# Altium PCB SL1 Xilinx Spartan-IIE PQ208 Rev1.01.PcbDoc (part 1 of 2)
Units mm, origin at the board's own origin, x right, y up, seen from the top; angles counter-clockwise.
Board outline 180.01 x 50.51 mm, 2 copper layers (Top Layer, Bottom Layer), stack 1.646 mm thick; 115 components, 126 nets, 642 pads, 225 vias.
Unrouted connection lines stored in the file: 2.
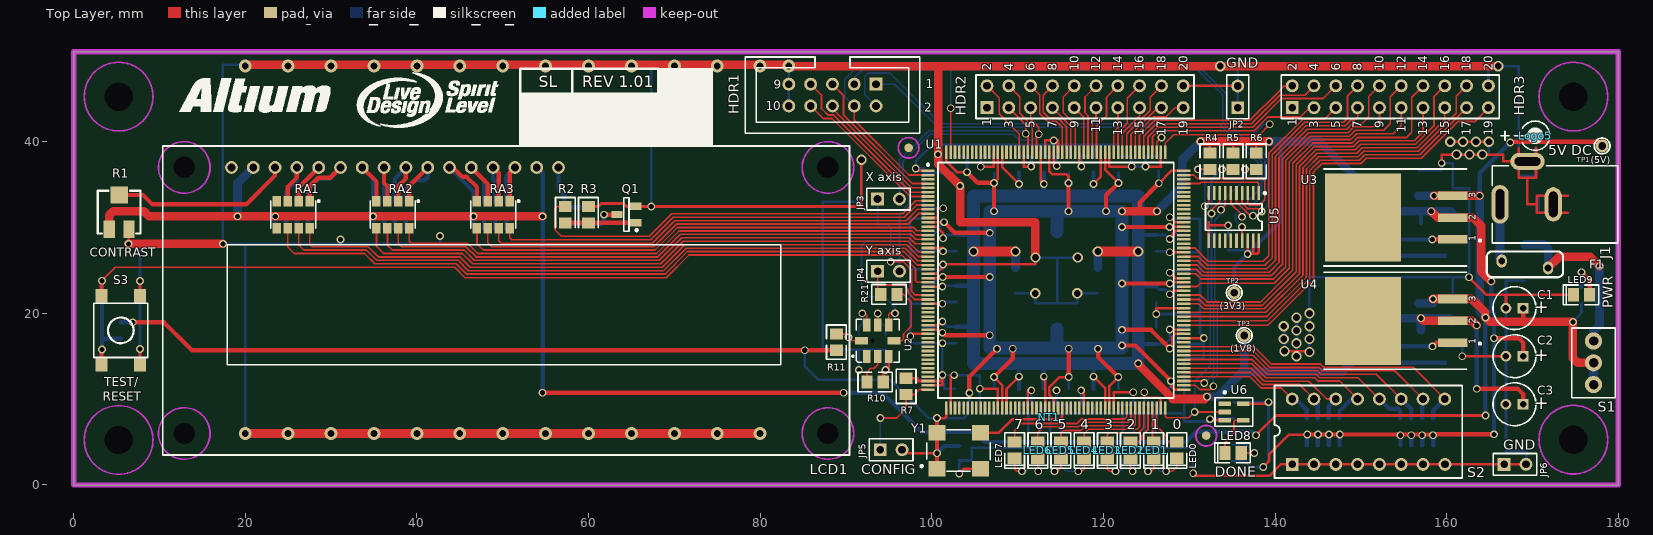
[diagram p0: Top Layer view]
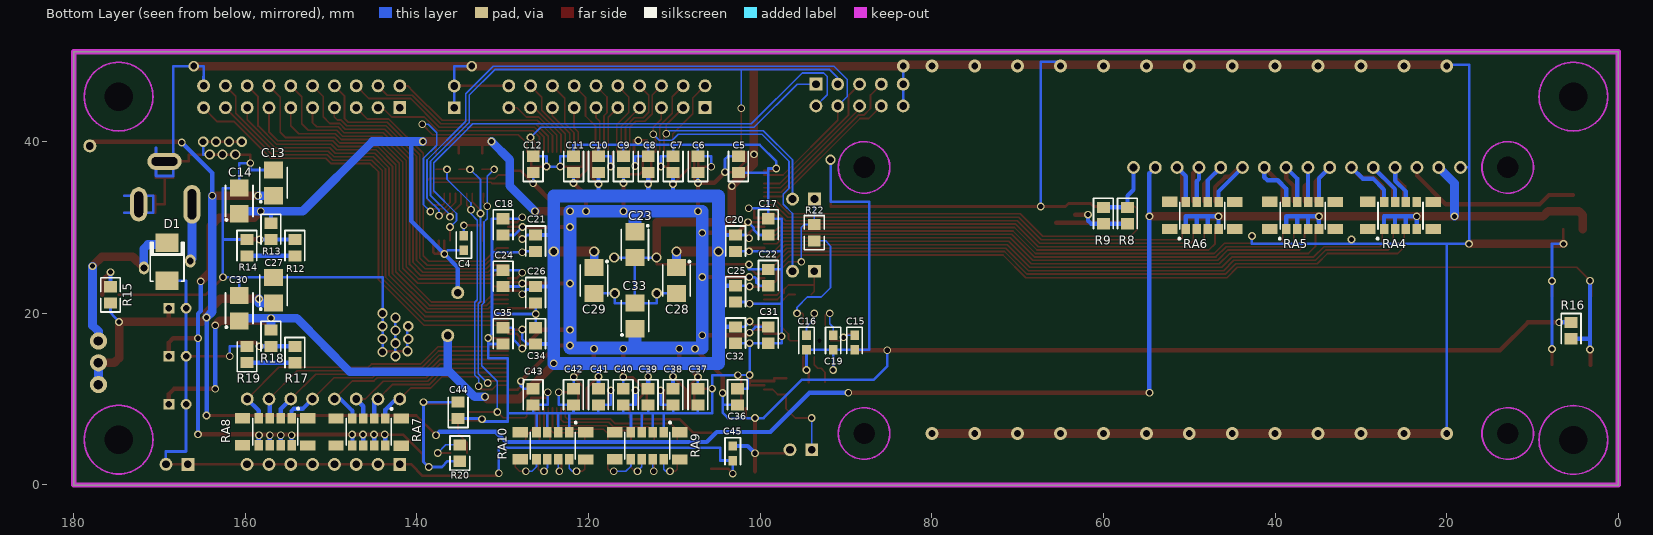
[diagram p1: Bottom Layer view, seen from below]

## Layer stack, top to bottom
Top Solder: solder mask 0.0102, Solder Resist, Dk 3.5
Top Layer: signal copper 0.0356
Dielectric1: core 1.5748, FR-4, Dk 4.8
Bottom Layer: signal copper 0.0356
Bottom Solder: solder mask 0.0102, Solder Resist, Dk 3.5

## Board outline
0,-0.005 cw(c0,0) -0.005,0 -0.005,50.5 cw(c0,50.5) 0,50.505 180,50.505 cw(c180,50.5) 180.005,50.5 180.005,0 cw(c180,0) 180,-0.005

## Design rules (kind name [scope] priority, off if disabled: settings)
Clearance "Clearance_Power Polygon" [inpolygon and innetclass('Power')] p1: gap=0.3 ignorepadtopadclearanceinfootprint=FALSE except(0: Arc-Hole Track-Hole SMDPad-Hole THPad-Hole Via-Hole Fill-Hole Poly-Hole Region-Hole Text-Hole)
Clearance [All] p2: gap=0.2 ignorepadtopadclearanceinfootprint=FALSE except(0: Arc-Hole Track-Hole SMDPad-Hole THPad-Hole Via-Hole Fill-Hole Poly-Hole Region-Hole Text-Hole) // General
ComponentClearance ComponentClearance_D1_F1 [InComponent('D1') vs InComponent('F1')] p1 off: gap=0.03 collisioncheckmode=3 verticalgap=0.254 showdistances=FALSE
ComponentClearance ComponentClearance_JP4_R21 [InComponent('JP4') vs InComponent('R21')] p2 off: gap=0.07 collisioncheckmode=3 verticalgap=0.254 showdistances=FALSE
ComponentClearance ComponentClearance_LCD1_U2 [InComponent('LCD1') vs InComponent('U2')] p3 off: gap=0.09 collisioncheckmode=3 verticalgap=0.254 showdistances=FALSE
ComponentClearance ComponentClearance_U1_U6 [InComponent('U1') vs InComponent('U6')] p4 off: gap=0.1 collisioncheckmode=3 verticalgap=0.254 showdistances=FALSE
ComponentClearance ComponentClearance_S2 [InComponent('S2') vs InComponent('RA7') Or InComponent('RA8')] p5 off: gap=0.1 collisioncheckmode=3 verticalgap=0.254 showdistances=FALSE // Why is such a small clearance necessary?
ComponentClearance ComponentClearance_LCD1_R11 [InComponent('LCD1') vs InComponent('R11')] p6 off: gap=0.16 collisioncheckmode=3 verticalgap=0.254 showdistances=FALSE
ComponentClearance ComponentClearance_J1_Logo5 [InComponent('J1') vs InComponent('Logo5')] p7 off: gap=0.19 collisioncheckmode=3 verticalgap=0.254 showdistances=FALSE
ComponentClearance ComponentClearance_R2_R3 [InComponent('R2') vs InComponent('R3')] p8 off: gap=0.19 collisioncheckmode=3 verticalgap=0.254 showdistances=FALSE
ComponentClearance ComponentClearance_R5 [InComponent('R5') vs InComponent('R4') Or InComponent('R6')] p9 off: gap=0.19 collisioncheckmode=3 verticalgap=0.254 showdistances=FALSE
ComponentClearance ComponentClearance_LEDs [HasFootprint('SMD _LED') vs HasFootprint('SMD _LED')] p10 off: gap=0.19 collisioncheckmode=3 verticalgap=0.254 showdistances=FALSE
ComponentClearance ComponentClearance_R7_R10 [InComponent('R7') vs InComponent('R10')] p11 off: gap=0.24 collisioncheckmode=3 verticalgap=0.254 showdistances=FALSE
ComponentClearance ComponentClearance_U1 [InComponent('U1') vs Not InComponent('NT1') && Not InComponent('LED8')] p12 off: gap=0.254 collisioncheckmode=3 verticalgap=0.254 showdistances=FALSE
ComponentClearance ComponentClearance_General [Not InComponent('U1') vs Not InComponent('U1')] p13 off: gap=0.254 collisioncheckmode=3 verticalgap=0.254 showdistances=FALSE
ComponentClearance ComponentClearance_Default [All] p14: gap=0.127 collisioncheckmode=3 verticalgap=0.254 showdistances=FALSE
FabricationTestPointUsage TestPointUsage [All] p1 off: valid=0 allowmultiple=FALSE
FabricationTestpoint Testpoint [All] p1 off: side=3 testpointundercomponent=TRUE minsize=1.016 maxsize=2.54 preferedsize=1.524 minholesize=0 maxholesize=1.016 preferedholesize=0.813 testpointgrid=0.025 allowsidetop=TRUE allowsidebottom=TRUE usegrid=TRUE gridtolerance=0
HoleSize [All] p1: absolutevalues=TRUE maxlimit=3.302 minlimit=0 maxpercent=80.000 minpercent=20.000
PlaneConnect [All] p1: planeconnectstyle=Relief reliefexpansion=0.3 reliefentries=4 reliefconductorwidth=0.2 reliefairgap=0.2
PolygonConnect PolygonConnect_Power [innetclass('Power')] p1: connectstyle=Relief reliefconductorwidth=0.3 reliefentries=4 polygonreliefangle="90 Angle" airgapwidth=0.254
PolygonConnect [All] p2: connectstyle=Relief reliefconductorwidth=0.2 reliefentries=4 polygonreliefangle="90 Angle" airgapwidth=0.254
RoutingVias RoutingVias_Power [innetclass('Power')] p1: holewidth=0.6 width=0.9 viastyle="Through Hole" minholewidth=0.6 minwidth=0.9 maxholewidth=0.8 maxwidth=1.5
RoutingVias [All] p2: holewidth=0.6 width=0.9 viastyle="Through Hole" minholewidth=0.6 minwidth=0.9 maxholewidth=0.6 maxwidth=0.9
SilkToSolderMaskClearance SilkscreenOverComponentPads [IsPad] p1: minsilkscreentomaskgap=0.254 clearancetoexposedcopper=TRUE
SolderMaskExpansion SolderMaskExpansion_Power_Vias [isvia] p1: expansion=0 istentingtop=FALSE
SolderMaskExpansion [All] p2: expansion=0.1 istentingtop=FALSE
Width Width_Power [innetclass('Power') and not inpolygon] p1: maxlimit=2 minlimit=0.3 preferedwidth=0.3
Width [All] p2: maxlimit=2 minlimit=0.2 preferedwidth=0.2
24 further rules are at their usual default settings.

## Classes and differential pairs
component class U_SL_LCD_SW_LED: LCD1 LED0 LED1 LED2 LED3 LED4 LED5 LED6 LED7 Q1 R1 R2 R3 R8 R9 R16 RA1 RA2 RA3 RA4 RA5 RA6 RA7 RA8 RA9 RA10 S2 S3
component class U_SL_FPGA_Auto_2E: U1
component class U_SL_Config: C4 C44 LED8 R4 R5 R6 R20 U5 U6
component class SL_FPGA_Manual_2E: C1 C2 C3 C5 C6 C7 C8 C9 C10 C11 C12 C13 C14 C17 C18 C20 C21 C22 C23 C24 C25 C26 C27 C28 C29 C30 C31 C32 C33 C34 C35 C36 C37 C38 C39 C40 C41 C42 C43 D1 F1 J1 JP2 JP6 LED9 R12 R13 R14 R15 R17 R18 R19 S1 TP1 TP2 TP3 U3 U4
net class SW[7..0]: SW0 SW1 SW2 SW3 SW4 SW5 SW6 SW7
net class LEDS[7..0]: LEDS0 LEDS1 LEDS2 LEDS3 LEDS4 LEDS5 LEDS6 LEDS7
net class LCD_DB[7..0]: LCD_DB0 LCD_DB1 LCD_DB2 LCD_DB3 LCD_DB4 LCD_DB5 LCD_DB6 LCD_DB7
net class Power: 5V GND VCCINT VCCO

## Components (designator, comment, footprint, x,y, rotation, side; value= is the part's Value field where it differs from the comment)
C1 "100uF 16V" CAPPR2-5X6.8 167.9,20.6 r180 top
C2 "100uF 16V" CAPPR2-5X6.8 167.9,15 r180 top
C3 "100uF 16V" CAPPR2-5X6.8 167.9,9.4 r180 top
C4 "10nF" CC1608-0603 134.525,28.2 r90 bottom
C5 "0.1uF" CC2012-0805 102.55,37.35 r90 bottom
C6 "0.1uF" CC2012-0805 107.25,37.35 r90 bottom
C7 "0.1uF" CC2012-0805 110.15,37.35 r90 bottom
C8 "0.1uF" CC2012-0805 113.05,37.35 r90 bottom
C9 "0.1uF" CC2012-0805 115.95,37.35 r90 bottom
C10 "0.1uF" CC2012-0805 118.85,37.35 r90 bottom
C11 "0.1uF" CC2012-0805 121.75,37.35 r90 bottom
C12 "0.1uF" CC2012-0805 126.45,37.35 r90 bottom
C13 "10uF" MCCT-B 156.7,35.2 r90 bottom
C14 "10uF" MCCT-B 160.7,33.1 r90 bottom
C15 "100nF" CC1608-0603 89,16.6 r270 bottom
C16 "100nF" CC1608-0603 94.6,16.6 r270 bottom
C17 "0.1uF" CC2012-0805 99.05,30.075 r270 bottom
C18 "0.1uF" CC2012-0805 129.95,30.075 r270 bottom
C19 "100nF" CC1608-0603 91.5,16.6 r270 bottom
C20 "0.1uF" CC2012-0805 102.85,28.175 r270 bottom
C21 "0.1uF" CC2012-0805 126.15,28.175 r270 bottom
C22 "0.1uF" CC2012-0805 99.05,24.175 r270 bottom
C23 "10uF" MCCT-B 114.6,28 r270 bottom
C24 "0.1uF" CC2012-0805 129.95,24.075 r270 bottom
C25 "0.1uF" CC2012-0805 102.85,22.275 r270 bottom
C26 "0.1uF" CC2012-0805 126.15,22.175 r270 bottom
C27 "10uF" MCCT-B 156.7,22.7 r90 bottom
C28 "10uF" MCCT-B 109.75,23.825 r270 bottom
C29 "10uF" MCCT-B 119.35,23.825 r270 bottom
C30 "10uF" MCCT-B 160.7,20.6 r90 bottom
C31 "0.1uF" CC2012-0805 99.05,17.475 r270 bottom
C32 "0.1uF" CC2012-0805 102.85,17.475 r270 bottom
C33 "10uF" MCCT-B 114.6,19.7 r90 bottom
C34 "0.1uF" CC2012-0805 126.15,17.375 r270 bottom
C35 "0.1uF" CC2012-0805 129.95,17.375 r270 bottom
C36 "0.1uF" CC2012-0805 102.65,10.275 r270 bottom
C37 "0.1uF" CC2012-0805 107.25,10.275 r270 bottom
C38 "0.1uF" CC2012-0805 110.15,10.275 r270 bottom
C39 "0.1uF" CC2012-0805 113.05,10.275 r270 bottom
C40 "0.1uF" CC2012-0805 115.95,10.275 r270 bottom
C41 "0.1uF" CC2012-0805 118.85,10.275 r270 bottom
C42 "0.1uF" CC2012-0805 121.75,10.275 r270 bottom
C43 "0.1uF" CC2012-0805 126.45,10.275 r270 bottom
C44 "0.1uF" CC2012-0805 135.2,8.7 r90 bottom
C45 "10nF" CC1608-0603 103.2,3.7 r270 bottom
D1 "SM6T6V8A" DO214 169.1,25.999 r90 bottom
F1 "Polyswitch, 1.1A" RUE160_0.2 169.1,25.7 r0 top
HDR1 "Header 5X2" HDR2X5_LP 93.5,46.7 r0 top
HDR2 "Header 10X2" HDR2X10 106.44,43.96 r0 top locked
HDR3 "Header 10X2" HDR2X10 142,43.96 r0 top locked
J1 "KLD-0202-B" KLD-0202 179.9,32.7 r180 top
JP2 "GND" HDR1X2 135.65,43.96 r90 top locked
JP3 "X axis" HDR1X2 93.693,33.31 r0 top
JP4 "Y axis" HDR1X2 93.7,24.9 r0 top
JP5 "CONFIG" HDR1X2 94,4.1 r0 top
JP6 "GND" HDR1X2 166.7,2.4 r0 top
LCD1 "162A" 162A 18.4,37 r0 top locked
LED0 "HSMH-C170" "SMD _LED" 128.55,4.075 r90 top
LED1 "HSMH-C170" "SMD _LED" 125.85,4.075 r90 top
LED2 "HSMH-C170" "SMD _LED" 123.15,4.075 r90 top
LED3 "HSMH-C170" "SMD _LED" 120.45,4.075 r90 top
LED4 "HSMH-C170" "SMD _LED" 117.75,4.075 r90 top
LED5 "HSMH-C170" "SMD _LED" 115.05,4.075 r90 top
LED6 "HSMH-C170" "SMD _LED" 112.35,4.075 r90 top
LED7 "HSMH-C170" "SMD _LED" 109.65,4.075 r90 top
LED8 "HSMH-C170" "SMD _LED" 135.1,3.725 r0 top
LED9 "HSMH-C170" "SMD _LED" 175.7,22.15 r0 top
Logo5 "5V" "5V SYMBOL" 170.3,40.7 r0 top
NT1 "GND" NT 113.686,8.174 r270 top net-tie
Q1 "2N7002" SO-G3 64.4,31.5 r90 top
R1 "20K" POT4MM-2 5.3,31.8 r90 top
R2 "560R" CC2012-0805 57.3,31.5 r270 top
R3 "10K" CC2012-0805 60,31.5 r270 top
R4 "4K7" CR2012-0805 132.4,37.725 r270 top
R5 "4K7" CR2012-0805 135.1,37.725 r270 top
R6 "4K7" CR2012-0805 137.8,37.725 r270 top
R7 "1K" CR2012-0805 97,11.5 r270 top
R8 "68R" CC2012-0805 57.2,31.4 r270 bottom
R9 "68R" CC2012-0805 60,31.4 r270 bottom
R10 "680R" CR2012-0805 93.4,12 r180 top
R11 "0R" CR2012-0805 88.88,16.65 r90 top
R12 "100R" CC2012-0805 154.2,27.65 r270 bottom
R13 "120R" CC2012-0805 157,29.55 r270 bottom
R14 "100R" CC2012-0805 159.8,27.65 r270 bottom
R15 "270R" CR2012-0805 175.7,22.15 r270 bottom
R16 "4K7" CC2012-0805 5.5,18 r270 bottom
R17 "47R" CC2012-0805 154.2,15.2 r270 bottom
R18 "120R" CC2012-0805 157,17.1 r270 bottom
R19 "5R6" CC2012-0805 159.8,15.2 r90 bottom
R20 "270R" CR2012-0805 135,3.725 r270 bottom
R21 "100R" CR2012-0805 95,22.2 r0 top
R22 "100R" CR2012-0805 93.7,29.4 r270 bottom
RA1 "270R" MNR34 25.6,31.5 r270 top
RA2 "270R" MNR34 37.2,31.5 r270 top
RA3 "270R" MNR34 48.9,31.5 r270 top
RA4 "4K7" MNR34T 25.4,31.4 r270 bottom
RA5 "4K7" MNR34T 36.8,31.4 r270 bottom
RA6 "4K7" MNR34T 48.5,31.4 r270 bottom
RA7 "4K7" MNR34T 145.605,6.174 r90 bottom
RA8 "4K7" MNR34T 156.5,6.2 r90 bottom
RA9 "270R" MNR34T 113.15,4.575 r90 bottom
RA10 "270R" MNR34T 124.15,4.575 r90 bottom
S1 "TL36WW050" PCB_SWITCH 177.105,11.689 r90 top
S2 "A6ER-8104" DIP-16-KEY 142,2.4 r0 top
S3 "DTSM-61-NR" B3FS_SWITCH 5.5,18 r270 top
TP1 "(5V)" TP 178.1,39.5 r0 top
TP2 "(3V3)" TP 135.233,22.4 r0 top
TP3 "(1V8)" TP 136.4,17.4 r0 top
U1 "XC2S300E-6PQ208C" PQ208 114.45,23.875 r0 top locked
U2 "ADXL202E" E-8 93.7,16.8 r90 top
U3 "LM1084IS-ADJ" TO-263 160.7,28.62 r90 top
U4 "LM1084IS-ADJ" TO-263 160.7,16.6 r90 top
U5 "XCF02SVO20C" VO20 135.175,31.225 r180 top
U6 "SN74LVC1G04DBV" SO-G5/P.95 135.2,8.5 r270 top
Y1 "25MHz" QSMO_4200 100.6,1.5 r0 top

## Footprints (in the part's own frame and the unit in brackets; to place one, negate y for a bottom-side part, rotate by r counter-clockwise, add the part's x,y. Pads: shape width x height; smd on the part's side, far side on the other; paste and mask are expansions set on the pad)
"5V SYMBOL" [mm]
  silkscreen extent -4.01,-1.71 1.7,1.71
162A [mm]
  round 1.5 hole 0.9: 1(0,0) 2(2.54,0) 3(5.08,0) 4(7.62,0) 5(10.16,0) 6(12.7,0) 7(15.24,0) 8(17.78,0) 9(20.32,0) 10(22.86,0) 11(25.4,0) 12(27.94,0) 13(30.48,0) 14(33.02,0) 15(35.56,0) 16(38.1,0)
  round 2.3 hole 2.5 unplated: M1(-5.5,0) M2(69.5,0) M3(-5.5,-31) M4(69.5,-31)
  Keep-Out Layer circle w0.2: c69.5,0 r3
  Keep-Out Layer circle w0.2: c69.5,-31 r3
  Keep-Out Layer circle w0.2: c-5.5,-31 r3
  Keep-Out Layer circle w0.2: c-5.5,0 r3
  silkscreen extent -8,-33.5 72,2.5, body extent -8.01,-33.5 72,2.5, height 10.16
B3FS_SWITCH [mm]
  rect 1.6x1.4 smd: 1(3.998,-2.244) 2(-4.012,-2.244) 3(3.998,2.246) 4(-4.012,2.246)
  silkscreen extent -3.17,-3.15 3.14,3.16, body extent -4.57,-3.15 4.57,3.16, height 4.57
CAPPR2-5X6.8 [mm]
  rect 1.25x1.25 hole 0.75: 1(-0.994,-0.009)
  round 1.25 hole 0.75: 2(1.006,-0.009)
  silkscreen extent -2.49,-2.51 2.5,2.49, body extent -2.49,-2.51 2.51,2.49, height 10.16
CC1608-0603 [mm]
  rect 1.1x1 smd: 1(-0.843,0.001) 2(0.857,0.001)
  silkscreen extent -1.79,-0.9 1.31,0.9, body extent -1.46,-0.57 1.46,0.57, height 0.76
CC2012-0805 [mm]
  rect 1.3x1.5 smd: 1(-0.945,-0.007) 2(0.955,-0.007)
  silkscreen extent -1.99,-1.16 1.51,1.14, body extent -1.52,-0.7 1.52,0.7, height 0.76
CR2012-0805 [mm]
  rect 1.3x1.5 smd: 1(-0.946,0) 2(0.954,0)
  silkscreen extent -2,-1.15 2,1.15, body extent -1.52,-0.7 1.52,0.7, height 0.76
DIP-16-KEY [mm]
  rect 1.5x1.5 hole 0.9: 1(-0.011,0.001)
  round 1.5 hole 0.9: 2(2.529,0.001) 3(5.069,0.001) 4(7.609,0.001) 5(10.149,0.001) 6(12.689,0.001) 7(15.229,0.001) 8(17.789,0.001) 9(17.769,7.621) 10(15.229,7.621) 11(12.689,7.621) 12(10.149,7.621) 13(7.609,7.621) 14(5.069,7.621) 15(2.529,7.621) 16(-0.011,7.621)
  silkscreen extent -2.06,-1.59 19.82,9.2, body extent -2.03,-1.52 19.81,9.14, height 7.11
DO214 [mm]
  rect 2.159x2.7 smd: 1(-2.21,0.005) 2(2.235,0.005)
  silkscreen extent -2.27,-1.96 2.3,1.97, body extent -3.17,-1.27 3.17,1.27, height 1.27
E-8 [mil]
  round 15 hole 20 unplated: 0(-0.02,23.98)
  rect 60x35 smd: 1(-72.85,49.98) 2(-72.85,-0.02) 3(-72.85,-50.02) 5(72.82,-50.02) 6(72.82,-0.02) 7(72.82,49.98)
  rect 35x60 smd: 4(-0.02,-74.82) 8(-0.02,74.79)
  silkscreen extent -98,-98 99,118, body extent -95,-95 95,95, height 80
HDR1X2 [mm]
  rect 1.5x1.5 hole 0.9: 1(-0.011,0.007)
  round 1.5 hole 0.9: 2(2.529,0.007)
  silkscreen extent -1.28,-1.26 3.8,1.28, body extent -1.27,-1.27 3.81,1.27, height 10
HDR2X5_LP [mm]
  rect 1.5x1.5 hole 0.9: 1(0.003,0.004)
  round 1.5 hole 0.9: 2(0.003,-2.536) 3(-2.537,0.004) 4(-2.537,-2.536) 5(-5.077,0.004) 6(-5.077,-2.536) 7(-7.617,0.004) 8(-7.617,-2.536) 9(-10.157,0.004) 10(-10.157,-2.536)
  silkscreen extent -15.24,-5.71 5.08,3.18, body extent -15.24,-5.71 5.08,3.18, height 10
HDR2X10 [mm]
  rect 1.5x1.5 hole 0.9: 1(-0.011,0.007)
  round 1.5 hole 0.9: 2(-0.011,2.547) 3(2.529,0.007) 4(2.529,2.547) 5(5.069,0.007) 6(5.069,2.547) 7(7.609,0.007) 8(7.609,2.547) 9(10.149,0.007) 10(10.149,2.547) 11(12.689,0.007) 12(12.689,2.547) 13(15.229,0.007) 14(15.229,2.547) 15(17.769,0.007) 16(17.769,2.547) 17(20.309,0.007) 18(20.309,2.547) 19(22.849,0.007) 20(22.849,2.547)
  silkscreen extent -1.28,-1.26 24.12,3.82, body extent -1.27,-1.27 24.13,3.81, height 10
KLD-0202 [mm]
  oval 2x4.5 hole 1 slot 3.5 at 90 deg: 1(13.692,-0.001)
  oval 2x4 hole 1 slot 3 at 90 deg: 2(7.492,-0.001)
  oval 4x2 hole 1 slot 3 at 0 deg: 3(10.492,-5.001)
  silkscreen extent -0.01,-4.5 14.59,4.5, body extent 0,-4.44 14.6,4.45, height 7.62
MCCT-B [mm]
  rect 2x2.2 smd: 1(-1.505,-0.002) 2(1.495,-0.002)
  silkscreen extent -2.3,-1.6 1.8,1.6, body extent -2.29,-0.89 2.29,0.89, height 1.27
MNR34 [mm]
  rect 1.2x1 smd: 1(-1.578,1.898) 2(-1.578,0.628) 3(-1.578,-0.642) 4(-1.578,-1.912) 5(1.572,-1.912) 6(1.572,-0.642) 7(1.572,0.628) 8(1.572,1.898)
  silkscreen extent -1.68,-2.62 1.55,3.06, body extent -2.03,-2.29 2.03,2.29, height 1.27
MNR34T [mm]
  rect 1.2x1 smd: 1(1.575,-1.896) 2(1.575,-0.626) 3(1.575,0.644) 4(1.575,1.914) 5(-1.575,1.914) 6(-1.575,0.644) 7(-1.575,-0.626) 8(-1.575,-1.896)
  rect 1.2x1.8 smd: STP(-1.6,-3.801) STP(-1.575,3.819) STP(1.575,-3.801) STP(1.575,3.819)
  silkscreen extent -1.55,-2.76 2.79,2.62, body extent -1.65,-2.71 1.68,2.72, height 2
NT [mm]
  rect 0.2x0.2 smd: 1(0.01,0.011) 2(0.51,0.011)
  Top Layer lines w0.3: 0.51,0.011 0.01,0.011
PCB_SWITCH [mm]
  round 2 hole 1.1: 1(0.011,0.005) 2(2.551,0.005) 3(5.091,0.005)
  silkscreen extent -1.54,-2.53 6.59,2.55, body extent -1.52,-2.54 6.6,2.54, height 15
POT4MM-2 [mm]
  rect 2x1.3 smd: CCW(-2.008,-1.162) CW(-2.008,1.138)
  rect 2x2 smd: W(1.992,-0.012)
  silkscreen extent -2.51,-2.51 2.49,2.49, body extent -2.92,-2.41 2.92,2.41, height 3.05
PQ208 [mm]
  rect 1.55x0.3 smd: 1(-14.902,12.738) 2(-14.902,12.238) 3(-14.902,11.738) 4(-14.902,11.238) 5(-14.902,10.738) 6(-14.902,10.238) 7(-14.902,9.738) 8(-14.902,9.238) 9(-14.902,8.738) 10(-14.902,8.238) 11(-14.902,7.738) 12(-14.902,7.238) 13(-14.902,6.738) 14(-14.902,6.238) 15(-14.902,5.738) 16(-14.902,5.238) 17(-14.902,4.738) 18(-14.902,4.238) 19(-14.902,3.738) 20(-14.902,3.238) 21(-14.902,2.738) 22(-14.902,2.238) 23(-14.902,1.738) 24(-14.902,1.238) 25(-14.902,0.738) 26(-14.902,0.238) 27(-14.902,-0.262) 28(-14.902,-0.762) 29(-14.902,-1.262) 30(-14.902,-1.762) 31(-14.902,-2.262) 32(-14.902,-2.762) 33(-14.902,-3.262) 34(-14.902,-3.762) 35(-14.902,-4.262) 36(-14.902,-4.762) 37(-14.902,-5.262) 38(-14.902,-5.762) 39(-14.902,-6.262) 40(-14.902,-6.762) 41(-14.902,-7.262) 42(-14.902,-7.762) 43(-14.902,-8.262) 44(-14.902,-8.762) 45(-14.902,-9.262) 46(-14.902,-9.762) 47(-14.902,-10.262) 48(-14.902,-10.762) 49(-14.902,-11.262) 50(-14.902,-11.762) 51(-14.902,-12.262) 52(-14.902,-12.762) 105(14.898,-12.762) 106(14.898,-12.262) 107(14.898,-11.762) 108(14.898,-11.262) 109(14.898,-10.762) 110(14.898,-10.262) 111(14.898,-9.762) 112(14.898,-9.262) 113(14.898,-8.762) 114(14.898,-8.262) 115(14.898,-7.762) 116(14.898,-7.262) 117(14.898,-6.762) 118(14.898,-6.262) 119(14.898,-5.762) 120(14.898,-5.262) 121(14.898,-4.762) 122(14.898,-4.262) 123(14.898,-3.762) 124(14.898,-3.262) 125(14.898,-2.762) 126(14.898,-2.262) 127(14.898,-1.762) 128(14.898,-1.262) 129(14.898,-0.762) 130(14.898,-0.262) 131(14.898,0.238) 132(14.898,0.738) 133(14.898,1.238) 134(14.898,1.738) 135(14.898,2.238) 136(14.898,2.738) 137(14.898,3.238) 138(14.898,3.738) 139(14.898,4.238) 140(14.898,4.738) 141(14.898,5.238) 142(14.898,5.738) 143(14.898,6.238) 144(14.898,6.738) 145(14.898,7.238) 146(14.898,7.738) 147(14.898,8.238) 148(14.898,8.738) 149(14.898,9.238) 150(14.898,9.738) 151(14.898,10.238) 152(14.898,10.738) 153(14.898,11.238) 154(14.898,11.738) 155(14.898,12.238) 156(14.898,12.738)
  rect 0.3x1.55 smd: 53(-12.752,-14.912) 54(-12.252,-14.912) 55(-11.752,-14.912) 56(-11.252,-14.912) 57(-10.752,-14.912) 58(-10.252,-14.912) 59(-9.752,-14.912) 60(-9.252,-14.912) 61(-8.752,-14.912) 62(-8.252,-14.912) 63(-7.752,-14.912) 64(-7.252,-14.912) 65(-6.752,-14.912) 66(-6.252,-14.912) 67(-5.752,-14.912) 68(-5.252,-14.912) 69(-4.752,-14.912) 70(-4.252,-14.912) 71(-3.752,-14.912) 72(-3.252,-14.912) 73(-2.752,-14.912) 74(-2.252,-14.912) 75(-1.752,-14.912) 76(-1.252,-14.912) 77(-0.752,-14.912) 78(-0.252,-14.912) 79(0.248,-14.912) 80(0.748,-14.912) 81(1.248,-14.912) 82(1.748,-14.912) 83(2.248,-14.912) 84(2.748,-14.912) 85(3.248,-14.912) 86(3.748,-14.912) 87(4.248,-14.912) 88(4.748,-14.912) 89(5.248,-14.912) 90(5.748,-14.912) 91(6.248,-14.912) 92(6.748,-14.912) 93(7.248,-14.912) 94(7.748,-14.912) 95(8.248,-14.912) 96(8.748,-14.912) 97(9.248,-14.912) 98(9.748,-14.912) 99(10.248,-14.912) 100(10.748,-14.912) 101(11.248,-14.912) 102(11.748,-14.912) 103(12.248,-14.912) 104(12.748,-14.912) 157(12.748,14.888) 158(12.248,14.888) 159(11.748,14.888) 160(11.248,14.888) 161(10.748,14.888) 162(10.248,14.888) 163(9.748,14.888) 164(9.248,14.888) 165(8.748,14.888) 166(8.248,14.888) 167(7.748,14.888) 168(7.248,14.888) 169(6.748,14.888) 170(6.248,14.888) 171(5.748,14.888) 172(5.248,14.888) 173(4.748,14.888) 174(4.248,14.888) 175(3.748,14.888) 176(3.248,14.888) 177(2.748,14.888) 178(2.248,14.888) 179(1.748,14.888) 180(1.248,14.888) 181(0.748,14.888) 182(0.248,14.888) 183(-0.252,14.888) 184(-0.752,14.888) 185(-1.252,14.888) 186(-1.752,14.888) 187(-2.252,14.888) 188(-2.752,14.888) 189(-3.252,14.888) 190(-3.752,14.888) 191(-4.252,14.888) 192(-4.752,14.888) 193(-5.252,14.888) 194(-5.752,14.888) 195(-6.252,14.888) 196(-6.752,14.888) 197(-7.252,14.888) 198(-7.752,14.888) 199(-8.252,14.888) 200(-8.752,14.888) 201(-9.252,14.888) 202(-9.752,14.888) 203(-10.252,14.888) 204(-10.752,14.888) 205(-11.252,14.888) 206(-11.752,14.888) 207(-12.252,14.888) 208(-12.752,14.888)
  round 1 smd: FID1(-17.152,15.413) FID2(17.523,-18.112)
  Top Layer keep-out circle w0.2: c17.523,-18.137 r1.2
  Top Layer keep-out circle w0.2: c-17.152,15.413 r1.2
  silkscreen extent -15.03,-13.74 13.72,13.71, body extent -15.35,-15.36 15.35,15.34, height 2.5
QSMO_4200 [mm]
  rect 2x1.8 smd: 1(-0.009,0.39) 2(5.071,0.39) 3(5.071,4.59) 4(-0.009,4.59)
  silkscreen extent -1.91,0.09 6.21,4.94, body extent -1.14,-0.32 6.1,5.3, height 1.5
RUE160_0.2 [mm]
  oval 1.2x1.5 hole 0.8: 1(-2.7,0.4) 2(2.7,-0.4)
  silkscreen extent -4.45,-1.5 4.45,1.5, body extent -4.45,-1.5 4.45,1.5, height 12
"SMD _LED" [mm]
  rect 1.3x1.6 smd: 1(0.948,0.006) 2(-0.952,0.006)
  silkscreen extent -2.13,-1.14 2,1.16, body extent -1.52,-0.64 1.52,0.64, height 1.27
SO-G3 [mm]
  rect 0.85x1.3 smd: 1(-0.939,-1.107) 2(0.961,-1.107) 3(0.011,1.093)
  silkscreen extent -1.94,-1.33 1.96,0.29, body extent -1.65,-1.52 1.65,1.51, height 2.54
SO-G5/P.95 [mm]
  rect 0.55x1.45 smd: 1(-0.954,-1.07) 2(-0.004,-1.07) 3(0.946,-1.07) 4(0.946,1.08) 5(-0.954,1.08)
  silkscreen extent -2.43,-2.19 1.65,2.21, body extent -1.27,-1.78 1.27,1.78, height 0.89
TO-263 [mm]
  rect 1x3.4 smd: 1(-0.006,0.009) 2(2.534,0.009) 3(5.074,0.009)
  rect 10.25x8.9 smd: 4(2.534,10.459)
  silkscreen extent -3.11,-3.29 8.19,15.01, body extent -2.29,-1.14 7.37,14.35, height 2.03
TP [mil]
  round 60 hole 35.43: 1(0.14,0.45)
  silkscreen extent -36,-36 36,36, body extent -36,-36 36,36
VO20 [mm]
  rect 0.3x1.65 smd: 1(-2.929,-2.778) 2(-2.279,-2.778) 3(-1.629,-2.778) 4(-0.979,-2.778) 5(-0.329,-2.778) 6(0.321,-2.778) 7(0.971,-2.778) 8(1.621,-2.778) 9(2.271,-2.778) 10(2.921,-2.778) 11(2.921,2.772) 12(2.271,2.772) 13(1.621,2.772) 14(0.971,2.772) 15(0.321,2.772) 16(-0.329,2.772) 17(-0.979,2.772) 18(-1.629,2.772) 19(-2.279,2.772) 20(-2.929,2.772)
  silkscreen extent -3.75,-2.9 3.3,1.55, body extent -3.3,-3.56 3.3,3.55, height 1.52

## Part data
C1 C2 C3 C13 C14 C23 C27 C28 C29 C30 C33: library part CAP_POLAR, "Polar Capacitor"
C4 C5 C6 C7 C8 C9 C10 C11 C12 C15 C16 C17 C18 C19 C20 C21 C22 C24 C25 C26 C31 C32 C34 C35 C36 C37 C38 C39 C40 C41 C42 C43 C44 C45: library part CAP, "Capacitor"
D1: library part BZG03C13, "Zener Diode, 6.2V, 5W"
F1: library part "Fuse 2", "Polyswitch 1.1A, Raychem RUE110"
HDR1: "Header, 5-Pin, Dual row"
HDR2 HDR3: "Header, 10-Pin, Dual row"
J1: "Low Voltage Power Supply Connector"
JP2 JP3 JP4 JP5 JP6 NT1: library part "Jumper, 2-Pin", "Jumper, 2-Pin"
LCD1: "16 char * 2 line LCD character display with b/light"
LED0 LED1 LED2 LED3 LED4 LED5 LED6 LED7 LED8 LED9: library part HSMX-C670, "Typical RED GaAs SMD LED Agilent make"
Q1: "N Channel Mosfet"
R1: library part "RPot SM", "Square Trimming Potentiometer"
R2 R3 R4 R5 R6 R7 R8 R9 R11 R12 R13 R14 R15 R16 R17 R18 R19 R20: library part RES, "Resistor"
R10 R21 R22: library part Res1, "Resistor"
RA1 RA2 RA3 RA4 RA5 RA6 RA7 RA8 RA9 RA10: library part MNR34, "3216x4 Resistor Array"
S1: library part PCB_MOUNT_SWITCH, "SPDT Subminiature Toggle Switch"
S2: "DIP Switch Side actuator long liver Piano Key"
S3: library part B3FS, "SPNA SMD Keyboard Switch"
TP1 TP2 TP3: library part TestPin
U1: "Spartan-IIE 1.8V FPGA, 208-Pin PQFP, Standard Performance, Commercial Grade"
U2: "Accelerometer with Digital Output"
U3 U4: "5A Low Dropout Possitive Regulators"
U5: "XCF00S Series, Platform Flash In-System Programmable Configuration 3.3V PROM, 20-Pin TSOP, 2-Megabit, Commercial Grade"
U6: library part SN74AHC1G04DBVR
Y1: library part QSMO_4200, "Surface Mount Crystal Oscillator"

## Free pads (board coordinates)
  round 0.9 hole 0.6 mask+0.1: 0(101.225,16.525)
  round 3 hole 3.3 unplated: M3(5.25,5.25) M3(5.25,45.25) M3(174.75,45.25) M3(174.75,5.275)

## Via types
v1: diameter 0.9, hole 0.6, Top Layer to Bottom Layer, tented both sides, 168 vias
v2: diameter 1.5, hole 0.8, Top Layer to Bottom Layer, tented both sides, 27 vias
v3: diameter 1.2, hole 0.8, Top Layer to Bottom Layer, 18 vias
v4: diameter 1.2, hole 0.8, Top Layer to Bottom Layer, tented both sides, 11 vias
v5: diameter 0.9, hole 0.6, Top Layer to Bottom Layer, 1 vias

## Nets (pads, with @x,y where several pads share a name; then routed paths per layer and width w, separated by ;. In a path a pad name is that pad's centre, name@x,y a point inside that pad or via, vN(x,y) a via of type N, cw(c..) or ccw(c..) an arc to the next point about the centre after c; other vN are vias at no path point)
5V: C1.1 C13.1 C27.1 LCD1.2 LCD1.15 R1.CW R15.2 RA4.1 RA4.2 RA4.3 RA4.4 RA5.1 RA5.2 RA5.3 RA5.4 RA6.1 RA6.2 RA6.3 RA6.4 S1.1 S1.2 TP1.1 U3.3 U4.3 | length 313.8
  Top Layer w0.3: v1(137.775,5.8) 140.075,8.1 v1(164.5,8.1)
  Top Layer w0.5: v1(54.65,10.75) v1(89.725,10.75) ; v1(167.4,39.9) 167.5,40 177.8,40 TP1.1@178.3,39.5 ; 168.9,19 C1.1@168.9,20.6
  Top Layer w1: R1.CW@4.15,29.8 4.15,31.45 4.6,31.9 8.2,31.9 8.8,31.3 v1(54.65,31.3) ; v1(158.4,21.675) 162.9,21.7 164.5,20.1 v1(164.5,19.525) 165.025,19 v1(174.7,19) 174.7,14.8 175.26,14.24 S1.2@177.1,14.24 ; v1(158.5,33.7) v1(163.85,33.7)
  Bottom Layer w0.3: v1(174.7,19) 175.7,20.1 R15.2@175.7,21.2
  Bottom Layer w0.5: RA4.4@23.495,29.825 v1(23.5,31.3) 27.31,31.3 ; RA4.3@24.765,29.825 24.765,31.295 ; RA4.2@26.035,29.825 26.035,31.295 ; RA4.1@27.305,29.825 27.305,31.295 ; RA5.4@34.895,29.825 v1(34.9,31.3) 38.71,31.3 ; RA5.3@36.165,29.825 36.165,31.295 ; RA5.2@37.435,29.825 37.435,31.295 ; RA5.1@38.705,29.825 38.705,31.295 ; RA6.4@46.595,29.825 v1(46.6,31.3) 50.41,31.3 ; RA6.3@47.865,29.825 47.865,31.295 ; RA6.2@49.135,29.825 49.135,31.295 ; RA6.1@50.405,29.825 50.405,31.295 ; LCD1.15@53.96,37 54.65,36.31 v1(54.65,10.75) ; v1(89.725,10.75) 94.25,10.75 98.8,6.2 105.05,6.175 106.225,5 129.6,5 130.8,6.2 137.375,6.2 v1(137.775,5.8) ; v1(163.85,33.7) 163.85,36.35 v1(167.4,39.9) ; v1(164.5,8.1) v1(164.5,19.525)
  Bottom Layer w1: v1(19.1,31.3) 19.1,35.16 LCD1.2@20.94,37 ; C27.1@156.7,21.2 158.4,21.2 v1(158.4,21.675) ; C13.1@156.7,33.7 v1(158.5,33.7) ; v1(163.85,33.7) 163.85,20.175 v1(164.5,19.525) ; S1.1@177.1,11.7 S1.2@177.1,14.24
CCLK: U1.155 U5.3 | length 15.5
  Top Layer w0.2: U1.155@129.35,36.125 130.525,36.125 130.95,35.7 138.55,35.7 138.8,35.45 138.8,33.2 138.225,32.625 136.975,32.625 136.8,32.8 U5.3@136.8,34
CLK_BRD: NT1.2 U1.80 Y1.3 | length 11.3
  Top Layer w0.3: Y1.3@105.68,6.1 107.8,6.1 109.35,7.65 114.95,7.65 115.198,7.898 U1.80@115.198,8.963
CLK_BRD_1: NT1.1 U1.77
DIN: U1.153 U5.1 | length 10
  Top Layer w0.2: U1.153@129.35,35.125 131.25,35.125 131.4,35.275 137.925,35.275 138.1,35.1 U5.1@138.1,34
DONE: R4.2 U1.104 U5.10 U6.2 | length 41
  Top Layer w0.2: U1.104@127.2,8.975 127.2,8 127.375,7.825 129.95,7.825 v1(130.625,8.5) U6.2@134.125,8.5 ; v1(131,36.775) R4.2@132.4,36.775 ; v1(131.8,32.475) 132.25,32.925 U5.10@132.25,34
  Bottom Layer w0.2: v1(130.625,8.5) 130.625,12.075 132.45,13.9 132.45,20.966 132.175,21.241 132.175,30.639 131.8,31.014 131.8,35.975 v1(131,36.775)
GND: C1.2 C2.2 C3.2 C4.2 C5.1 C6.2 C7.2 C8.2 C9.2 C10.2 C11.2 C12.2 C13.2 C14.2 C15.2 C16.2 C17.1 C18.1 C19.2 C20.2 C21.2 C22.1 C23.2 C24.1 C25.2 C26.2 C27.2 C28.2 C29.2 C30.2 C31.2 C32.2 C33.2 C34.1 C35.2 C36.1 C37.2 C38.2 C39.2 C40.2 C41.2 C42.2 C43.2 C44.1 C45.2 D1.1 HDR1.9 HDR1.10 HDR2.20 HDR3.20 J1.2 J1.3 JP2.1 JP2.2 JP6.1 JP6.2 LCD1.1 LED9.2 pad.0 Q1.2 R1.CCW R3.1 R7.1 R10.1 R14.1 R19.2 RA9.1 RA9.2 RA9.3 RA9.4 RA10.1 RA10.2 RA10.3 RA10.4 S2.1 S2.2 S2.3 S2.4 S2.5 S2.6 S2.7 S2.8 S3.3 S3.4 U1.1 U1.12 U1.19 U1.25 U1.32 U1.39 U1.50 U1.51 U1.54 U1.65 U1.72 U1.79 U1.85 U1.92 U1.103 U1.117 U1.124 U1.131 U1.137 U1.144 U1.158 U1.170 U1.177 U1.182 U1.183 U1.185 U1.190 U1.197 U2.3 U5.11 U6.3 Y1.2 | length 1070.9
  Top Layer w0.3: v1(6.4,28.1) 6.45,28.15 R1.CCW@6.45,29.8 ; S3.3@7.74,13.99 v1(7.74,15.84) ; S3.4@7.74,22 v1(7.74,23.76) ; R3.1@60,32.45 61.15,32.45 61.5,32.8 64.075,32.8 64.425,32.45 65.5,32.45 v1(67.3,32.45) 91.8,32.45 v4(91.8,37.9) ; R10.1@94.35,12 94.35,13.4 v1(94.6,13.4) 94.97,13.4 U2.3@94.97,14.95 ; R7.1@96.989,12.455 98.375,12.455 98.375,12.113 U1.50@99.548,12.113 101.225,12.113 ; v1(97.5,17.325) 97.5,17.613 U1.39@99.548,17.613 ; v1(98.125,36.875) 98.125,36.625 U1.1@99.55,36.625 ; U1.32@99.548,21.113 v1@101.225,21.113 ; U1.25@99.548,24.613 100.487,24.613 101.3,25.426 v1(101.3,25.7) 112.075,25.7 v4(112.075,26.5) ; U1.19@99.548,27.613 101.3,27.613 v1(101.3,27.225) ; U1.12@99.548,31.113 100.7,31.113 100.7,32.25 v1(101.325,32.25) ; U1.51@99.55,11.625 101.225,11.625 101.225,12.113 ; v1(101.225,12.825) 101.225,12.113 ; U1.54@102.198,9.022 102.198,12.8 v1(102.6,12.8) ; v1(103.2,1.325) 103.775,1.9 Y1.2@105.68,1.9 ; v1(105.6,11.225) 107.698,11.225 U1.65@107.698,8.963 ; v1(105.7,37.075) 107.198,37.075 U1.197@107.198,38.763 ; U1.190@110.698,38.763 110.698,37.1 v1(111.575,37.1) ; U1.72@111.198,8.963 111.198,11.025 v1(111.6,11.025) ; U1.185@113.198,38.763 113.198,40.15 ; 113.2,40.15 v1(114.2,40.15) 114.698,40.15 ; U1.183@114.198,38.763 114.198,37.173 v1(114.55,37.173) ; v1(114.525,11.025) v1@114.7,11.025 ; U1.182@114.698,38.763 114.698,40.15 ; 114.7,40.15 114.698,40.15 ; v1@117.198,37.1 U1.177@117.198,38.763 ; v1(117.4,11.025) v1@117.698,11.025 ; U1.85@117.698,8.963 v1@117.698,11.025 ; v1@117.7,11.025 v1@117.698,11.025 ; U1.170@120.698,38.763 120.698,37.1 v1(123.3,37.1) ; U1.92@121.198,8.963 121.198,10.8 v1(123.475,10.8) ; v1(124.75,10.8) 124.75,10.15 126.698,10.15 U1.103@126.698,8.963 ; v1(124.9,37.1) 126.698,37.1 ; v1(126.15,19.925) 126.15,20.613 U1.124@129.348,20.613 ; U1.158@126.698,38.763 126.698,37.1 ; 126.7,37.1 126.698,37.1 ; v1(127.725,24.725) 128.337,24.113 U1.131@129.348,24.113 ; v5(127.725,27.113) U1.137@129.348,27.113 ; v1(127.725,31.2) 128.312,30.613 U1.144@129.348,30.613 ; HDR2.20@129.3,46.5 JP2.2@135.65,46.5 ; U1.117@129.348,17.113 v1@131.7,17.113 ; v1(130.45,1.375) 130.7,1.075 139.325,1.075 140.65,2.4 S2.3@147.069,2.401 166.689,2.4 JP6.2@169.24,2.4 ; U5.11@132.25,28.45 132.25,30.25 ; 132.25,30.625 132.25,30.25 ; v1(132.4,7.675) 132.4,7.55 U6.3@134.125,7.55 ; v1(134.525,30.25) 132.25,30.25 ; v3(141.1,15.6) 143.9,15.6 v3(144,15.5) ; v3(142.5,15) v3@142.5,15.5 ; v1(159.4,37.5) 159.4,38.5 v3(161.15,38.5) v3(162.65,38.5) v3(164.15,38.5) 166.575,38.5 166.575,37.7 168.4,37.7 J1.3@168.4,37.5 ; v3(160.4,40) v3(161.9,40) v3(163.4,40) v3(164.9,40) ; v1(161.8,15) C2.2@166.9,15 ; v1(162.6,24.2) 164.65,22.15 166.9,22.15 ; C1.2@166.9,21 166.9,22.15 ; 168.4,39.255 168.4,35.8 169.4,35.8 ; 170.4,39.255 170.4,35.8 169.4,35.8 ; 172.45,22.15 174.75,22.15 166.9,22.15 ; 174.1,31.7 170.5,31.7 170.5,32.725 ; 174.1,33.7 172.408,33.7 170.5,33.7 170.5,32.725 ; 169.4,35.8 169.4,32.725 170.5,32.725
  Top Layer w1: v1(6.4,28.1) v1(17.4,28.1) ; v2(20,6) v2(25,6) v2(30,6) v2(35,6) v2(40,6) v2(45,6) v2(50,6) v2(55,6) v2(60,6) v2(65,6) v2(70,6) v2(75,6) v2(80,6) ; v2@20,48.95 40,48.95 55,48.95 v2@83.325,48.95 ; v2(83.325,48.8) 100.725,48.8 ; 100.725,48.805 100.725,48.8 ; v4(112.075,26.5) 112.075,30.6 103.3,30.6 v1(103.3,34.825) 100.725,37.4 v1(100.725,38.525) 100.725,48.8 ; v4(166,48.8) v4(133.6,48.8) 100.725,48.8
  Bottom Layer w0.3: v1(6.4,28.1) 7.74,28.1 v1(7.74,23.76) v1(7.74,15.84) ; LCD1.1@18.4,37 17.4,37 ; v2(20,6) 20,28.1 ; v2@20,48.95 17.4,48.95 17.4,37 ; v1(31.1,28.6) 31.1,28.1 ; v1(42.7,29) 42.7,28.1 31.1,28.1 ; v2@65,49.3 67.3,49.3 v1(67.3,32.45) ; HDR1.9@83.325,46.715 v2(83.325,48.8) v2@83.325,48.95 ; HDR1.10@83.34,44.16 HDR1.9@83.34,46.7 ; v1(91.5,13.4) C19.2@91.5,15.75 ; v4(91.8,37.9) 91.8,33.025 87.3,33.025 87.3,15.75 C19.2@91.5,15.75 ; v1@94.627,13.677 v1(94.6,13.4) 94.6,15.75 C19.2@91.5,15.75 ; v1(101.3,25.7) 101.3,25.125 99.05,25.125 97.5,25.125 ; v1(101.325,32.25) 99.05,32.25 ; C5.1@102.55,36.4 99.05,36.4 ; C36.1@102.65,11.225 101.47,11.225 101.47,12.58 v1(101.225,12.825) ; C32.2@102.85,16.525 pad.0@101.225,16.525 ; C25.2@102.85,21.325 101.425,21.325 v1(101.225,21.125) 97.5,21.125 ; C20.2@102.85,27.225 v1(101.3,27.225) 97.5,27.225 ; v1(103.2,1.325) 103.2,2.85 104.65,2.85 104.65,4.325 130.45,4.325 v1(130.45,1.375) ; v1(105.7,37.075) 105.7,38.3 107.25,38.3 107.25,39.625 ; C37.2@107.25,9.325 107.25,9.32 107.25,8.375 ; C28.2@109.75,22.325 v4(112.05,22.325) 112.05,21.2 C33.2@114.6,21.2 ; RA9.1@111.245,6.15 111.245,8.37 ; v1(111.575,37.1) 111.575,38.3 110.15,38.3 110.15,38.305 110.15,39.625 ; v1(111.6,11.025) 111.6,9.325 110.15,9.325 110.15,8.4 110.125,8.375 ; v4(112.075,26.5) C23.2@114.6,26.5 ; RA9.2@112.515,6.15 112.515,8.37 ; 113.05,8.375 C39.2@113.05,9.325 ; RA9.3@113.785,6.15 113.785,8.37 ; v1(114.2,40.15) 114.2,39.625 ; v1(114.525,11.025) 114.525,9.325 115.95,9.325 115.95,8.375 ; v1(114.55,37.173) 114.55,38.3 113.05,38.3 113.05,39.625 ; RA9.4@115.055,6.15 115.055,8.37 ; C9.2@115.95,38.3 115.95,39.625 ; v4(117,26.5) 114.602,26.5 C23.2@114.6,26.5 ; v1(117.4,11.025) 117.4,9.325 118.85,9.325 118.85,8.375 ; v1(117.425,37.1) 117.425,38.3 118.85,38.3 118.85,38.305 118.85,39.625 ; C29.2@119.35,22.325 v4(116.95,22.325) 116.95,21.2 C33.2@114.6,21.2 ; 121.75,8.375 121.75,9.325 123.475,9.325 v1(123.475,10.8) ; RA10.1@122.245,6.15 122.245,8.37 ; RA10.2@123.515,6.15 123.515,8.37 ; v1(124.75,10.8) 124.75,9.325 126.45,9.325 126.45,8.375 ; RA10.3@124.785,6.15 124.785,8.37 ; RA10.4@126.055,6.15 126.055,8.37 ; C34.1@126.15,18.325 v1(126.15,19.925) ; C26.2@126.15,21.225 v1(126.15,19.925) ; C21.2@126.157,27.22 127.272,27.219 127.379,27.113 v5(127.725,27.113) ; C12.2@126.45,38.3 124.9,38.3 v1(124.9,37.1) v1(123.3,37.1) 123.3,38.3 121.75,38.3 121.75,39.625 118.85,39.625 ; v1(127.725,24.725) 128.025,25.025 129.95,25.025 131.25,25.025 ; v5@127.725,27.125 131.25,27.125 ; v1(127.725,31.2) 127.9,31.025 129.95,31.025 131.25,31.025 131.25,25.025 ; C35.2@129.95,16.425 131.7,16.425 ; 131.25,19.925 v1(126.15,19.925) ; v4(133.6,48.8) 135.65,48.8 JP2.1@135.65,43.96 ; C4.2@134.525,29.05 v1(134.525,30.25) ; C44.1@135.2,7.75 132.725,7.75 v1(132.4,7.675) 132.4,7.4 129.4,7.4 129.4,8.375 ; v3(141,18.5) 141.1,18.4 v3(141.1,15.6) ; v3(142.5,15) v3(142.5,16.5) v3(142.5,18) v3(142.5,19.5) ; v3(144,15.5) v3(144,17) v3(144,18.5) v3(144,20) 144,24.2 156.7,24.2 160.7,24.2 ; C13.2@156.7,36.7 159.4,36.7 v1(159.4,37.5) 160.7,37.5 160.7,34.6 162.6,34.6 ; R19.2@159.8,16.15 161.8,16.15 v1(161.8,15) ; R14.1@159.8,28.6 162.6,28.6 ; C30.2@160.7,22.1 160.7,24.2 ; 162.55,34.6 162.6,34.6 ; v3(164.15,38.5) 164.9,38.5 v3(164.9,40) ; HDR3.20@164.86,46.5 164.86,46.507 164.85,48.8 v4(166,48.8) 168.4,48.8 168.4,36 170.4,36 170.4,37.701 170.4,39.3 ; D1.1@169.1,23.777 166.9,23.775 166.9,3.9 169.24,3.9 JP6.2@169.24,2.4 ; 174.1,31.7 170.7,31.7 170.7,33.7 172.408,33.7 174.1,33.7 ; 17.4,37 v1(17.4,28.1) 20,28.1 ; 20,28.1 31.1,28.1 ; 97.5,21.125 97.5,25.125 ; 97.5,21.125 v1(97.5,17.325) 97.5,16.525 99.05,16.525 pad.0@101.225,16.525 ; 97.5,25.125 97.5,27.225 ; 97.5,27.225 97.5,31.025 99.05,31.025 99.05,32.25 ; 99.05,32.25 99.05,36.4 ; 99.05,36.4 99.05,36.875 v1(98.125,36.875) 98.125,37.7 100.05,39.625 107.25,39.625 ; v1(101.225,12.825) pad.0@101.225,16.525 ; v1(101.225,12.825) v1(102.6,12.8) 105.6,12.8 v1(105.6,11.225) 105.6,8.375 107.25,8.375 ; 107.25,8.375 110.125,8.375 ; 107.25,39.625 110.15,39.625 ; 110.125,8.375 126.45,8.375 ; 110.15,39.625 113.05,39.625 ; 113.05,39.625 114.2,39.625 ; 114.2,39.625 115.95,39.625 ; C33.2@114.6,21.2 C23.2@114.6,26.5 ; 115.95,39.625 118.85,39.625 ; 126.45,8.375 129.4,8.375 ; 129.4,8.375 129.4,14.775 131.7,14.775 131.7,16.425 ; 131.25,25.025 131.25,17.675 131.7,17.225 v1(131.7,17.125) 131.7,16.425 ; 160.7,24.2 v1(162.6,24.2) 162.6,28.6 ; 162.6,28.6 162.6,34.6
  other v2: 20,48.8 25,48.8 30,48.8 35,48.8 40,48.8 45,48.8 50,48.8 55,48.8 60,48.8 65,48.8 70,48.8 75,48.8 80,48.8
  other v3: 141,17
HA2: HDR2.2 U1.191 | length 9.3
  Top Layer w0.2: HDR2.2@106.44,46.5 107.85,45.09 107.85,43.25 110.2,40.9 U1.191@110.2,38.775
HA3: HDR2.3 JP3.2 U1.189 | length 26.9
  Top Layer w0.2: HDR2.3@108.98,43.96 110.95,41.99 v1(110.95,40.925) 111.2,40.625 U1.189@111.2,38.775
  Bottom Layer w0.2: JP3.2@96.233,33.31 96.233,37.883 99.625,41.275 110.6,41.275 v1(110.95,40.925)
HA4: HDR2.4 U1.188 | length 8.9
  Top Layer w0.2: HDR2.4@108.98,46.5 110.25,45.23 110.25,43.304 111.7,41.854 U1.188@111.7,38.775
HA5: HDR2.5 JP4.2 U1.187 | length 36.9
  Top Layer w0.2: HDR2.5@111.52,43.96 111.52,42.6 112.45,41.67 v1(112.45,40.875) 112.2,40.625 U1.187@112.2,38.775
  Bottom Layer w0.2: JP4.2@96.233,24.91 96.233,31.633 97.3,32.7 97.3,33.9 96.633,34.567 96.633,37.718 99.791,40.875 109.55,40.875 110.25,40.175 111.75,40.175 v1(112.45,40.875)
HA6: HDR2.6 U1.181 | length 9.9
  Top Layer w0.2: HDR2.6@111.52,46.5 112.575,45.445 112.575,43.259 113.459,42.375 114.514,42.375 115.2,41.689 U1.181@115.2,38.775
HA7: HDR2.7 U1.179 | length 6.1
  Top Layer w0.2: HDR2.7@114.06,43.96 116.2,41.82 U1.179@116.2,38.775
HA8: HDR2.8 U1.180 | length 9.9
  Top Layer w0.2: HDR2.8@114.06,46.5 112.975,45.415 112.975,43.425 113.625,42.775 114.679,42.775 115.7,41.754 U1.180@115.7,38.775
HA9: HDR2.9 U1.176 | length 5.6
  Top Layer w0.2: HDR2.9@116.6,43.96 117.7,42.86 U1.176@117.7,38.775
HA10: HDR2.10 U1.178 | length 8.8
  Top Layer w0.2: HDR2.10@116.6,46.5 115.3,45.2 115.3,43.4 116.7,42 U1.178@116.7,38.775
HA11: HDR2.11 U1.174 | length 5.4
  Top Layer w0.2: U1.174@118.7,38.775 118.7,42.375 119.14,42.815 HDR2.11@119.14,43.96
HA12: HDR2.12 U1.175 | length 8.4
  Top Layer w0.2: U1.175@118.2,38.775 118.2,43.025 117.85,43.375 117.85,45.21 HDR2.12@119.14,46.5
HA13: HDR2.13 U1.169 | length 5.4
  Top Layer w0.2: U1.169@121.2,38.775 121.2,41.122 121.68,41.602 HDR2.13@121.68,43.96
HA14: HDR2.14 U1.173 | length 8.8
  Top Layer w0.2: U1.173@119.2,38.775 119.2,41.85 120.35,43 120.35,45.17 HDR2.14@121.68,46.5
HA15: HDR2.15 U1.167 | length 6
  Top Layer w0.2: U1.167@122.2,38.775 122.2,40.991 124.22,43.011 HDR2.15@124.22,43.96
HA16: HDR2.16 U1.168 | length 8.8
  Top Layer w0.2: U1.168@121.7,38.775 121.7,41.056 122.775,42.131 122.775,45.055 HDR2.16@124.22,46.5
HA17: HDR2.17 U1.165 | length 6.9
  Top Layer w0.2: U1.165@123.2,38.775 123.2,40.85 126.31,43.96 HDR2.17@126.76,43.96
HA18: HDR2.18 U1.166 | length 9.4
  Top Layer w0.2: U1.166@122.7,38.775 122.7,40.925 125.45,43.675 125.45,45.19 HDR2.18@126.76,46.5
HA19: HDR2.19 U1.164 | length 8.9
  Top Layer w0.2: U1.164@123.7,38.775 123.7,40.784 125.801,42.885 127.26,42.885 128.335,43.96 HDR2.19@129.3,43.96
HARD_TCK: HDR1.3 U1.207 U5.6 | length 75.3
  Top Layer w0.2: U1.207@102.2,38.775 v1(102.2,43.9) ; U5.6@134.85,34 134.85,32.769 136.144,31.475 v1(136.144,31.242)
  Bottom Layer w0.2: HDR1.3@90.96,46.7 90.96,47.46 91.9,48.4 130.934,48.4 133.9,45.434 133.9,42.225 ; v1(102.2,43.9) 102.2,48.4 ; 133.9,42.234 134.125,42.009 134.125,42 138.425,37.7 138.425,33.777 136.144,31.496 v1(136.144,31.242)
HARD_TDI: HDR1.1 U1.159 | length 37.8
  Top Layer w0.2: U1.159@126.2,38.775 126.2,39.95 v1(126.75,40.5)
  Bottom Layer w0.2: HDR1.1@93.5,46.7 95.7,46.7 100.725,41.675 125.575,41.675 v1(126.75,40.5)
HARD_TDO: HDR1.2 U5.17 | length 64.8
  Top Layer w0.2: U5.17@136.15,28.45 v1(136.15,30.05)
  Bottom Layer w0.2: HDR1.2@93.5,44.16 92.2,45.46 92.2,47.6 92.6,48 95.1,48 101.025,42.075 133.484,42.075 134.723,40.837 138.025,37.534 138.025,34.266 135.39,31.631 135.39,30.81 v1(136.15,30.05)
HARD_TMS: HDR1.4 U1.2 U5.5 | length 83.2
  Top Layer w0.2: HDR1.4@90.96,44.16 90.96,42.5 97.335,36.125 U1.2@99.55,36.125 ; U5.5@135.5,34 135.5,32.95 137.081,31.369 v1(137.414,31.369)
  Bottom Layer w0.2: HDR1.4@90.96,44.16 89.85,45.27 89.85,47.25 91.405,48.805 131.095,48.805 134.3,45.6 134.3,42.4 138.825,37.875 138.825,33.415 137.414,32.004 v1(137.414,31.369)
HB2: HDR3.2 U1.163 | length 22.1
  Top Layer w0.2: U1.163@124.2,38.775 124.2,40.719 125.967,42.485 137.054,42.485 140.402,45.833 141.069,46.5 HDR3.2@142,46.5
HB3: HDR3.3 U1.160 | length 22
  Top Layer w0.2: U1.160@125.7,38.775 125.7,40.522 126.464,41.285 137.551,41.285 139.149,42.883 142.933,42.883 144.01,43.96 HDR3.3@144.54,43.96
HB4: HDR3.4 U1.162 | length 24.1
  Top Layer w0.2: U1.162@124.7,38.775 124.7,40.653 126.132,42.085 137.22,42.085 140.559,45.425 143.465,45.425 HDR3.4@144.54,46.5
HB5: HDR3.5 U1.138 | length 32.8
  Top Layer w0.2: U1.138@129.35,27.625 130.616,27.625 132.162,26.079 138.629,26.079 139.25,26.7 139.25,38.634 143.266,42.65 145.77,42.65 HDR3.5@147.08,43.96
HB6: HDR3.6 U1.161 | length 26.1
  Top Layer w0.2: U1.161@125.2,38.775 125.2,40.587 126.298,41.685 137.385,41.685 140.725,45.025 145.605,45.025 HDR3.6@147.08,46.5
HB7: HDR3.7 U1.135 | length 36.2
  Top Layer w0.2: U1.135@129.35,26.125 130.984,26.125 131.909,25.2 139.05,25.2 140.05,26.2 140.05,38.303 143.597,41.85 148.166,41.85 148.825,42.509 148.825,42.525 149.275,42.525 149.62,42.87 HDR3.7@149.62,43.96
HB8: HDR3.8 U1.136 | length 37.9
  Top Layer w0.2: U1.136@129.35,26.625 131.05,26.625 132.075,25.6 138.8,25.6 139.65,26.45 139.65,38.469 143.431,42.25 148,42.25 148.425,42.675 148.425,45.305 HDR3.8@149.62,46.5
HB9: HDR3.9 U1.133 | length 39.4
  Top Layer w0.2: U1.133@129.35,25.125 130.825,25.125 131.55,24.4 139.55,24.4 140.85,25.7 140.85,34.825 140.85,37.972 143.928,41.05 148.497,41.05 149.172,41.725 151.675,41.725 152.16,42.21 HDR3.9@152.16,43.96
HB10: HDR3.10 U1.134 | length 40.7
  Top Layer w0.2: U1.134@129.35,25.625 130.891,25.625 131.716,24.8 139.3,24.8 140.45,25.95 140.45,38.137 143.763,41.45 148.331,41.45 149.006,42.125 150.15,42.125 150.925,42.9 150.925,45.265 HDR3.10@152.16,46.5
HB11: HDR3.11 U1.129 | length 42.5
  Top Layer w0.2: U1.129@129.35,23.125 130.925,23.125 131.305,23.505 139.905,23.505 141.65,25.25 141.65,35.4 141.65,37.64 144.26,40.25 148.828,40.25 149.503,40.925 153.75,40.925 154.7,41.875 HDR3.11@154.7,43.96
HB12: HDR3.12 U1.132 | length 44
  Top Layer w0.2: U1.132@129.35,24.625 130.75,24.625 131.375,24 139.8,24 141.25,25.45 141.25,37.806 144.094,40.65 148.663,40.65 149.338,41.325 152.675,41.325 153.425,42.075 153.425,45.225 HDR3.12@154.7,46.5
HB13: HDR3.13 U1.126 | length 46.7
  Top Layer w0.2: U1.126@129.35,21.625 131.175,21.625 131.875,20.925 138.525,20.925 142.45,24.85 142.45,35.175 142.45,37.309 144.591,39.45 149.16,39.45 149.81,40.1 156.197,40.1 157.24,41.143 HDR3.13@157.24,43.96
HB14: HDR3.14 U1.127 | length 48.3
  Top Layer w0.2: U1.127@129.35,22.125 131.275,22.125 132.075,21.325 138.325,21.325 142.05,25.05 142.05,35.2 142.05,37.475 144.425,39.85 148.994,39.85 149.644,40.5 155.325,40.5 155.925,41.1 155.925,45.185 HDR3.14@157.24,46.5
HB15: HDR3.15 U1.123 | length 48.5
  Top Layer w0.2: U1.123@129.35,20.125 138.925,20.125 143.25,24.45 143.25,36.977 144.923,38.65 149.491,38.65 150.141,39.3 156.529,39.3 159.78,42.551 HDR3.15@159.78,43.96
HB16: HDR3.16 U1.125 | length 50.7
  Top Layer w0.2: U1.125@129.35,21.125 131.075,21.125 131.675,20.525 138.725,20.525 142.85,24.65 142.85,34.7 142.85,37.143 144.757,39.05 149.325,39.05 149.975,39.7 156.363,39.7 158.5,41.837 158.5,45.22 HDR3.16@159.78,46.5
